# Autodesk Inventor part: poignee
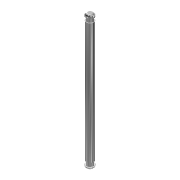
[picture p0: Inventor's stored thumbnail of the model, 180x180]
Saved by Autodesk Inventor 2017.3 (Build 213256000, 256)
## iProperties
Shininess: 20.0
Angle Display Precision: 2
Document Length Units: 11269
Document Angle Units: 11279
Document Time Units: 11290
Document Mass Units: 11283
Document Length Units Precision: 3
Document Angle Units Precision: 2
Created: 2002-04
Part Number: poignee
Material: Générique
Document SubType Name: Modélisation
Designer: Administrateur
Density: 1 g/cm^3
Appearance: Chrome - Noir
Density: 0.0
Volumn: 0.0
Area: 0.0
PropertySet Name: Model Information
Control State: 0
Master: False
Checked Out: False
Author: Administrateur
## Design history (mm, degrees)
sketch "Esquisse1"
  geometry: C1 r 6.25 at (25.52, -11.124)
  constraints: 1 centre point
  dimensions: "d0" = 12.5 diameter of C1
extrude "Extrusion1" new body sketch "Esquisse1" distance "d1" = 200; taper "d2" = 0 deg
sketch "Esquisse2"
  geometry: C1 r 6.25 at (0, 0) reference; C2 r 5 at (0, 0)
  constraints: 1 centre point, 1 coincident
  dimensions: "d3" = 10 diameter of C2
extrude "Extrusion2" join sketch "Esquisse2" distance "d4" = 7; taper "d5" = 0 deg
sketch "Esquisse3"
  geometry: C1 r 5 at (0, 0) reference; C2 r 7 at (0, 0)
  constraints: 1 centre point, 1 coincident
  dimensions: "d6" = 14 diameter of C2
extrude "Extrusion3" join sketch "Esquisse3" distance "d7" = 4; taper "d8" = 0 deg
fillet "Congé1" dims "d9" = 4
sketch "Esquisse4"
  geometry: C1 r 6.25 at (0, 0) reference; C2 r 5 at (0, 0)
  constraints: 1 centre point, 1 coincident
  dimensions: "d10" = 10 diameter of C2
extrude "Extrusion4" join sketch "Esquisse4" distance "d11" = 7; taper "d12" = 0 deg
sketch "Esquisse5"
  geometry: C1 r 5 at (0, 0) reference; C2 r 7 at (0, 0)
  constraints: 1 centre point, 1 coincident
  dimensions: "d13" = 14 diameter of C2
extrude "Extrusion5" join sketch "Esquisse5" distance "d14" = 4; taper "d15" = 0 deg
fillet "Congé2" dims "d16" = 4
node "Solide1"
node "Corps solides"
node "Corps surfaciques"
